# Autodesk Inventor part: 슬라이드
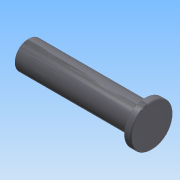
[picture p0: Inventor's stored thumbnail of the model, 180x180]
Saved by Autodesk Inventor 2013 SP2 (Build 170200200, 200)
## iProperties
Created: 2013-06
Part Number: 슬라이드
Document SubType Name: Modeling
Designer: SeoGD™[esajin.kr]
Density: 7.86 g/cm^3
Material: 강철, 연강
Mass: 1603.27 g
Surface Area: 269.019 cm^2
Volume: 203.978 cm^3
Author: SeoGD™[esajin.kr]
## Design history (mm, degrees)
sketch "스케치1"
  geometry: L1 (-75, 162)-(-75, 58) reference; L2 (-148, 110)-(22, 110); L3 (-148, 110)-(-148, 129); L4 (-148, 129)-(12, 129); L5 (12, 129)-(12, 139); L6 (12, 139)-(22, 139); L7 (22, 139)-(22, 110); 2 further points
  constraints: 12 end point, 3 parallel, 3 perpendicular, 1 midpoint, 1 point on line
  dimensions: "d0" = 58 diameter of L6 L2; "d1" = 38 diameter of L4 L2; "d2" = 10 distance of L5.end L6.end; "d3" = 170 distance of L2.start L2.end; "d4" = 73 distance between parallel lines of L3 L1
revolve "회전1" sketch "스케치1" stored, may be unused: angle "d5" = 90 deg
hole "구멍1" diameter "d11" = 13.376; stored, may be unused: countersink angle "d15" = 90 deg, drill point angle "d17" = 118 deg; dims "d9" = 10, "d10" = 10, "d12" = 22, "d13" = 4, "d14" = 2, "d16" = 25
chamfer "모따기1" distance "d6" = 1; stored, may be unused: second distance "d7" = 2, angle "d8" = 45 deg
node "솔리드1"
node "참조1"
